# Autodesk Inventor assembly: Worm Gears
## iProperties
Created: 2008-01
Part Number: Worm Gears
Document SubType Name: Assembly
Designer: eruiz-tagle
Mass: 4.82459 g
Surface Area: 11.9593 cm^2
Volume: 0.613815 cm^3
Density: 7.86 g/cm^3
ClientObjectVersion: 1
Author: eruiz-tagle
